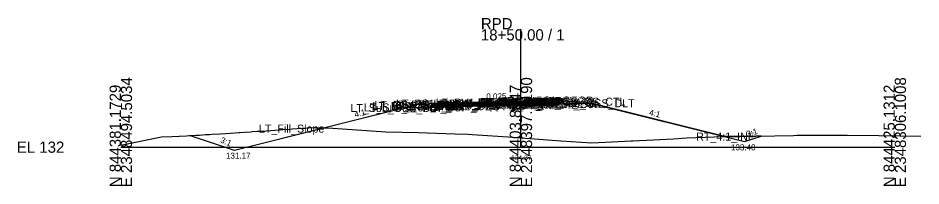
# Model space of a CAD drawing. Extents: x -26 to 2348536, y -510 to 844755.
# Drawn here: x -25.7 to 200, y 3490.3 to 3532.3 of the extents above; entities that cross this region are included whole.
import ezdxf

# ---------------------------------------------------------------- set-up
doc = ezdxf.new("R2010")
doc.units = 0
for name, color, linetype in [('Default', 7, 'Continuous'), ('Exist Cross Section Cell', 7, 'Continuous'), ('Exist XS Center Line Elevation Label', 7, 'Continuous'), ('Exist XS Ground Line', 7, 'Continuous'), ('Prop CMT Pvmt Course 1', 7, 'Continuous'), ('Prop CMT Pvmt Course 2', 7, 'Continuous'), ('Prop CMT Pvmt Course 3', 7, 'Continuous'), ('Prop CMT Pvmt Surface', 7, 'Continuous'), ('Prop CMT Pvmt Surface Shoulder', 7, 'Continuous'), ('Prop CMT Shld Paved Course 1', 7, 'Continuous'), ('Prop CMT Shld Paved Course 2', 7, 'Continuous'), ('Prop CMT Shld Paved Course 3', 7, 'Continuous'), ('Prop CMT Slope Grass', 7, 'Continuous'), ('Prop CMT Subgrade Earthwork', 7, 'Continuous'), ('Prop XS Ditch Standard Text', 7, 'Continuous'), ('Prop XS Earthwork Shape', 7, 'Continuous'), ('Prop XS SE Text', 7, 'Continuous'), ('Prop XS Side Slope Text', 7, 'Continuous'), ('Scratch_Level_0', 7, 'Continuous')]:
    doc.layers.add(name, color=color, linetype=linetype)

msp = doc.modelspace()

# ---------------------------------------------------------------- linework, layer by layer
at = {"layer": 'Exist Cross Section Cell'}
for p, q in [((100, 3500), (100, 3529.47)), ((0, 3500), (100, 3500)), ((100, 3500), (193.46, 3500))]:
    msp.add_line(p, q, dxfattribs=at)
at = {"layer": 'Exist XS Ground Line'}
msp.add_lwpolyline([(0, 3500.51), (10.15, 3502.56), (12.79, 3502.69), (18.16, 3502.95), (18.8, 3502.98), (19.7, 3503.02), (21.14, 3503.15), (21.74, 3503.17), (22.2, 3503.19), (22.83, 3503.23), (24.74, 3503.35), (26.21, 3503.45), (27.34, 3503.53), (29.54, 3503.67), (29.85, 3503.69), (30.9, 3503.75), (32.46, 3503.85), (32.83, 3503.88), (34.07, 3503.98), (34.97, 3504.01), (36.29, 3504.11), (37.5, 3504.2), (39.51, 3504.34), (40.1, 3504.38), (40.47, 3504.41), (42.13, 3504.52), (42.91, 3504.57), (45.25, 3504.72), (46.17, 3504.78), (47.64, 3504.88), (48.7, 3504.86), (50.45, 3504.85), (51.72, 3504.81), (57.85, 3504.43), (66.27, 3503.86), (74.4, 3503.64), (76.54, 3503.58), (83.55, 3503.35), (86.81, 3503.25), (87.8, 3503.2), (98.03, 3502.53), (100, 3502.37), (104.51, 3502), (109.99, 3501.59), (117.75, 3501.09), (127.56, 3501.58), (127.98, 3501.6), (138.15, 3502.12), (141.37, 3502.31), (148.42, 3502.61), (154.77, 3502.68), (158.69, 3502.76), (168.16, 3502.94), (168.96, 3502.96), (171.57, 3502.98), (179.23, 3503.04), (181.56, 3503.02), (189.49, 3502.93), (194.95, 3502.85), (200, 3502.79)], dxfattribs=at)
at = {"layer": 'Prop CMT Pvmt Course 1'}
for p, q in [((100, 3511.45), (88, 3511.15)), ((88, 3510.9), (100, 3511.2)), ((88, 3511.15), (88, 3510.9)), ((100, 3511.45), (104, 3511.55)), ((100, 3511.2), (100, 3511.45)), ((100, 3511.2), (100, 3511.45)), ((100, 3511.2), (100, 3511.32)), ((100, 3511.32), (100, 3511.32)), ((100, 3511.32), (100, 3511.2)), ((100, 3511.2), (100, 3511.32)), ((100, 3511.32), (100, 3511.32)), ((100, 3511.32), (100, 3511.2)), ((104, 3511.3), (100, 3511.2)), ((100, 3511.2), (100, 3511.2)), ((100, 3511.2), (100, 3511.2)), ((104, 3511.55), (104, 3511.3))]:
    msp.add_line(p, q, dxfattribs=at)
at = {"layer": 'Prop CMT Pvmt Course 2'}
for p, q in [((100, 3511.2), (88, 3510.9)), ((88, 3510.9), (88, 3510.56)), ((88, 3510.56), (100, 3510.86)), ((100, 3511.2), (104, 3511.3)), ((100, 3510.86), (100, 3511.2)), ((100, 3510.86), (100, 3511.2)), ((104, 3510.96), (100, 3510.86)), ((104, 3511.3), (104, 3510.96))]:
    msp.add_line(p, q, dxfattribs=at)
at = {"layer": 'Prop CMT Pvmt Course 3'}
for p, q in [((100, 3510.86), (88, 3510.56)), ((88, 3510.56), (88, 3510.23)), ((88, 3510.23), (100, 3510.53)), ((100, 3510.86), (104, 3510.96)), ((100, 3510.53), (100, 3510.86)), ((100, 3510.53), (100, 3510.86)), ((104, 3510.63), (100, 3510.53)), ((104, 3510.96), (104, 3510.63))]:
    msp.add_line(p, q, dxfattribs=at)
at = {"layer": 'Prop CMT Pvmt Surface'}
for q in [(88, 3511.15), (104, 3511.55)]:
    msp.add_line((100, 3511.45), q, dxfattribs=at)
at = {"layer": 'Prop CMT Pvmt Surface Shoulder'}
for p, q in [((88, 3511.15), (78, 3510.9)), ((104, 3511.55), (108, 3511.65))]:
    msp.add_line(p, q, dxfattribs=at)
at = {"layer": 'Prop CMT Shld Paved Course 1'}
for p, q in [((78, 3510.9), (77.74, 3510.64)), ((77.74, 3510.64), (88, 3510.9)), ((88, 3511.15), (78, 3510.9)), ((88, 3510.9), (88, 3511.15)), ((104, 3511.55), (108, 3511.65)), ((104, 3511.3), (104, 3511.55)), ((108.24, 3511.4), (104, 3511.3)), ((108, 3511.65), (108.24, 3511.4))]:
    msp.add_line(p, q, dxfattribs=at)
at = {"layer": 'Prop CMT Shld Paved Course 2'}
for p, q in [((77.74, 3510.64), (77.4, 3510.3)), ((77.4, 3510.3), (88, 3510.56)), ((88, 3510.9), (77.74, 3510.64)), ((88, 3510.56), (88, 3510.9)), ((104, 3511.3), (108.24, 3511.4)), ((104, 3510.96), (104, 3511.3)), ((108.57, 3511.08), (104, 3510.96)), ((108.24, 3511.4), (108.57, 3511.08))]:
    msp.add_line(p, q, dxfattribs=at)
at = {"layer": 'Prop CMT Shld Paved Course 3'}
for p, q in [((76.9, 3510.29), (76.56, 3509.94)), ((76.56, 3509.94), (88, 3510.23)), ((77.4, 3510.3), (76.9, 3510.29)), ((88, 3510.56), (77.4, 3510.3)), ((88, 3510.23), (88, 3510.56)), ((104, 3510.96), (108.57, 3511.08)), ((104, 3510.63), (104, 3510.96)), ((109.39, 3510.77), (104, 3510.63)), ((108.57, 3511.08), (109.07, 3511.09)), ((109.07, 3511.09), (109.39, 3510.77))]:
    msp.add_line(p, q, dxfattribs=at)
at = {"layer": 'Prop CMT Slope Grass'}
for p, q in [((74, 3510.58), (28.37, 3499.17)), ((78, 3510.9), (74, 3510.58)), ((108, 3511.65), (116, 3511.37)), ((116, 3511.37), (155.87, 3501.4)), ((28.37, 3499.17), (17.17, 3502.9)), ((155.87, 3501.4), (160.02, 3502.78))]:
    msp.add_line(p, q, dxfattribs=at)
at = {"layer": 'Prop CMT Subgrade Earthwork'}
for p, q in [((76.56, 3509.94), (70.9, 3509.8)), ((88, 3510.23), (76.56, 3509.94)), ((100, 3510.53), (88, 3510.23)), ((100, 3510.53), (104, 3510.63)), ((104, 3510.63), (109.39, 3510.77)), ((109.39, 3510.77), (117.59, 3510.97))]:
    msp.add_line(p, q, dxfattribs=at)
at = {"layer": 'Prop XS Earthwork Shape'}
for points in [[(141.37, 3502.31), (148.42, 3502.61), (150.9, 3502.64), (117.59, 3510.97), (109.39, 3510.77), (104, 3510.63), (100, 3510.53), (88, 3510.23), (76.56, 3509.94), (70.9, 3509.8), (51.03, 3504.83), (51.72, 3504.81), (57.85, 3504.43), (66.27, 3503.86), (74.4, 3503.64), (76.54, 3503.58), (83.55, 3503.35), (86.81, 3503.25), (87.8, 3503.2), (98.03, 3502.53), (100, 3502.37), (104.51, 3502), (109.99, 3501.59), (117.75, 3501.09), (127.56, 3501.58), (127.98, 3501.6), (138.15, 3502.12)], [(28.37, 3499.17), (17.17, 3502.9), (18.16, 3502.95), (18.8, 3502.98), (19.7, 3503.02), (21.14, 3503.15), (21.74, 3503.17), (22.2, 3503.19), (22.83, 3503.23), (24.74, 3503.35), (26.21, 3503.45), (27.34, 3503.53), (29.54, 3503.67), (29.85, 3503.69), (30.9, 3503.75), (32.46, 3503.85), (32.83, 3503.88), (34.07, 3503.98), (34.97, 3504.01), (36.29, 3504.11), (37.5, 3504.2), (39.51, 3504.34), (40.1, 3504.38), (40.47, 3504.41), (42.13, 3504.52), (42.91, 3504.57), (45.25, 3504.72), (46.17, 3504.78), (47.64, 3504.88), (48.7, 3504.86), (50.45, 3504.85), (51.03, 3504.83)], [(155.87, 3501.4), (160.02, 3502.78), (158.69, 3502.76), (154.77, 3502.68), (150.9, 3502.64)]]:
    msp.add_lwpolyline(points, close=True, dxfattribs=at)

# ---------------------------------------------------------------- texts
at = {"layer": 'Default'}
msp.add_text('-', height=0.0001, dxfattribs=at).set_placement((0, 3500))
at = {"layer": 'Exist Cross Section Cell'}
for s, p in [('RPD', (90, 3529.47)), ('18+50.00 / 1', (90, 3526.67)), ('EL 132', (-26, 3498.6))]:
    msp.add_text(s, height=2.8, dxfattribs=at).set_placement(p)
for s, p in [('E 2348494.5034', (2.8, 3490)), ('E 2348397.1190', (102.8, 3490)), ('E 2348306.1008', (196.26, 3490)), ('N 844381.1729', (0, 3490)), ('N 844403.8947', (100, 3490)), ('N 844425.1312', (193.46, 3490))]:
    msp.add_text(s, height=2.8, rotation=90, dxfattribs=at).set_placement(p)
at = {"layer": 'Exist XS Center Line Elevation Label'}
msp.add_text('134.37', height=1.2, dxfattribs=at).set_placement((97.55, 3496.77))
at = {"layer": 'Prop XS Ditch Standard Text'}
for s, p in [('133.40', (152.52, 3499.2)), ('131.17', (26.28, 3497.12))]:
    msp.add_text(s, height=1.5, dxfattribs=at).set_placement(p)
at = {"layer": 'Prop XS SE Text'}
msp.add_text('0.025', height=1.5, rotation=1.4321, dxfattribs=at).set_placement((91.38, 3511.9))
at = {"layer": 'Prop XS Side Slope Text'}
for s, rotation, p in [('4:1', 14.0362, (58.58, 3507.4)), ('4:1', 345.9638, (131.95, 3508.03)), ('3:1', 17.8017, (156.63, 3502.5)), ('3:1', 337.031, (24.72, 3501.23))]:
    msp.add_text(s, height=1.5, rotation=rotation, dxfattribs=at).set_placement(p)
at = {"layer": 'Scratch_Level_0'}
for s, p in [('LT_PS1_OEOP', (68.8, 3509.9)), ('LT_PV2_OEOT', (78.17, 3509.9)), ('LT_PV1_OEOT', (78.74, 3510.15)), ('RT_PV2_OEEOP', (89.26, 3510.2)), ('RT_PV3_OEEOP', (89.26, 3509.86)), ('LT_PV2_OEEOP', (89.31, 3510.2)), ('LT_PV3_OEEOP', (89.31, 3509.86)), ('RT_PV1_OEEOP', (89.83, 3510.32)), ('LT_PV1_OEEOP', (89.87, 3510.32)), ('RT_PV2_IEEOP', (89.91, 3510.2)), ('LT_PV2_IEEOP', (89.95, 3510.2)), ('RT_PV1_IEEOP', (90.47, 3510.32)), ('LT_PV1_IEEOP', (90.52, 3510.32)), ('RT_Sub_Trench_Out', (93.55, 3509.77)), ('PV2_PGL', (93.91, 3510.2)), ('RT_PV2_OEOT', (94.13, 3510.3)), ('RT_PV3_OEOT', (94.13, 3509.96)), ('PV1_PGL', (94.47, 3510.45)), ('RT_PV1_OEOT', (94.69, 3510.55)), ('RT_PS3_Shelf_Out', (95.01, 3510.09)), ('RT_PS2_OEOP', (98.43, 3510.4)), ('RT_PS1_OEOP', (98.76, 3510.65)), ('RT_PS3_OEOP', (98.76, 3510.08)), ('RT_Sub_OSS_DLT', (104.94, 3509.97)), ('RT_GS_OS_CTL', (105.32, 3510.37)), ('LT_Sub_OSS_DLT', (57.37, 3508.78)), ('LT_Sub_Trench_Out', (60.76, 3508.94)), ('LT_PS3_Shelf_Out', (62.89, 3509.29)), ('LT_GS_OS_CTL', (63.37, 3509.58)), ('LT_PS3_OEOP', (67.64, 3509.3)), ('LT_PS2_OEOP', (67.98, 3509.64)), ('LT_Sub_OEOT', (78.08, 3509.23)), ('LT_PV3_OEOT', (78.17, 3509.56)), ('RT_Sub_OEEOP', (89.17, 3509.53)), ('LT_Sub_OEEOP', (89.21, 3509.53)), ('RT_Sub_OEOT', (94.03, 3509.63)), ('LT_Fill_Slope', (34.52, 3503.64)), ('RT_4:1_INF', (143.79, 3501.64))]:
    msp.add_text(s, height=2, dxfattribs=at).set_placement(p)

doc.saveas('drawing.dxf')
